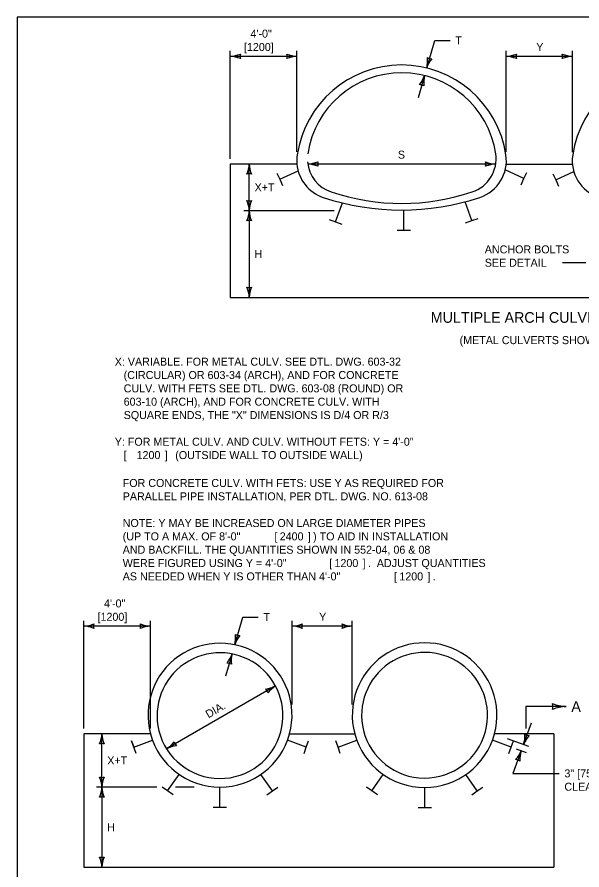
# Model space of a CAD drawing. Extents: x 49988.5 to 50021, y 49987.6 to 50011.4.
# Drawn here: x 50000.34 to 50004.57, y 50004.87 to 50011.26 of the extents above; entities that cross this region are included whole.
import ezdxf

# ---------------------------------------------------------------- set-up
doc = ezdxf.new("R2010")
doc.units = 0
for name, color, linetype in [('Level 1', 7, 'Continuous'), ('Level 2', 7, 'Continuous'), ('Level 3', 7, 'Continuous'), ('Level 6', 7, 'Continuous')]:
    doc.layers.add(name, color=color, linetype=linetype)

msp = doc.modelspace()

# ---------------------------------------------------------------- linework, layer by layer
at = {"layer": 'Level 1'}
for p, q in [((50002.4328, 50010.1613), (50001.9329, 50010.1613)), ((50001.9329, 50010.1613), (50001.9329, 50009.1613)), ((50002.3043, 50010.0468), (50002.4418, 50010.1108)), ((50004.1337, 50010.0516), (50003.994, 50010.1169)), ((50004.0014, 50010.1613), (50004.4972, 50010.1613)), ((50002.2831, 50010.0921), (50002.3043, 50010.0468)), ((50002.3043, 50010.0468), (50002.3255, 50010.0015)), ((50004.1128, 50010.0064), (50004.1337, 50010.0516)), ((50004.1337, 50010.0516), (50004.1549, 50010.097)), ((50004.3508, 50010.087), (50004.372, 50010.0417)), ((50004.372, 50010.0417), (50004.5079, 50010.105)), ((50004.372, 50010.0417), (50004.3932, 50009.9964)), ((50002.7226, 50009.7286), (50002.7738, 50009.8696)), ((50003.744, 50009.737), (50003.6928, 50009.8778)), ((50003.2338, 50009.6659), (50003.2338, 50009.8159)), ((50002.6756, 50009.7458), (50002.7226, 50009.7286)), ((50002.7226, 50009.7286), (50002.7695, 50009.7115)), ((50003.6971, 50009.7198), (50003.744, 50009.737)), ((50003.744, 50009.737), (50003.7911, 50009.754)), ((50003.1838, 50009.6659), (50003.2338, 50009.6659)), ((50003.2338, 50009.6659), (50003.2838, 50009.6659)), ((50001.9329, 50009.1613), (50006.5462, 50009.1613)), ((50001.3352, 50005.8907), (50000.8356, 50005.8907)), ((50000.8356, 50005.8907), (50000.8356, 50004.8907)), ((50002.378, 50005.8907), (50002.866, 50005.8907)), ((50004.3574, 50005.8907), (50003.9135, 50005.8907)), ((50004.3574, 50005.8907), (50004.3574, 50004.8907)), ((50001.2103, 50005.7899), (50001.193, 50005.8369)), ((50001.193, 50005.8369), (50001.2103, 50005.7899)), ((50001.2103, 50005.7899), (50001.3507, 50005.842)), ((50002.5029, 50005.7899), (50002.3624, 50005.842)), ((50002.5029, 50005.7899), (50002.5202, 50005.8369)), ((50002.7409, 50005.7899), (50002.7236, 50005.8369)), ((50002.7409, 50005.7899), (50002.8814, 50005.8421)), ((50004.0385, 50005.7899), (50003.898, 50005.842)), ((50004.0385, 50005.7899), (50004.0558, 50005.8369)), ((50001.2273, 50005.7431), (50001.2103, 50005.7899)), ((50002.4859, 50005.7431), (50002.5029, 50005.7899)), ((50002.7579, 50005.7431), (50002.7409, 50005.7899)), ((50004.0215, 50005.7431), (50004.0385, 50005.7899)), ((50001.4641, 50005.4622), (50001.5501, 50005.5858)), ((50002.2491, 50005.4622), (50002.1631, 50005.5859)), ((50002.9947, 50005.4622), (50003.0803, 50005.5853)), ((50003.7847, 50005.4622), (50003.6991, 50005.5853)), ((50001.4641, 50005.4622), (50001.4231, 50005.4907)), ((50001.5049, 50005.4336), (50001.4641, 50005.4622)), ((50001.8551, 50005.3403), (50001.8551, 50005.4904)), ((50002.2083, 50005.4336), (50002.2491, 50005.4622)), ((50002.2491, 50005.4622), (50002.2901, 50005.4907)), ((50002.9947, 50005.4622), (50002.9537, 50005.4907)), ((50003.0355, 50005.4336), (50002.9947, 50005.4622)), ((50003.3902, 50005.3383), (50003.3902, 50005.4883)), ((50003.7439, 50005.4336), (50003.7847, 50005.4622)), ((50003.7847, 50005.4622), (50003.8257, 50005.4907)), ((50001.8051, 50005.3403), (50001.8551, 50005.3403)), ((50001.8551, 50005.3403), (50001.9051, 50005.3403)), ((50003.3402, 50005.3383), (50003.3902, 50005.3383)), ((50003.3902, 50005.3383), (50003.4402, 50005.3383)), ((50000.8356, 50004.8907), (50004.3574, 50004.8907))]:
    msp.add_line(p, q, dxfattribs=at)
msp.add_lwpolyline([(50008.6146, 50011.2628), (50000.3356, 50011.2628), (50000.3356, 50000.0624), (50008.6146, 50000.0624)], close=True, dxfattribs=at)
for centre, radius, start, end in [((50003.2171, 50010.1128), 0.7909, 8.49352, 171.50648), ((50005.2815, 50010.1128), 0.7909, 8.49352, 171.50648), ((50003.2184, 50010.1334), 0.7118, 8.49352, 171.50648), ((50003.6637, 50010.1999), 0.2615, 288.43689, 8.49352), ((50002.7223, 50010.1867), 0.2906, 171.50648, 185.01191), ((50002.7731, 50010.1999), 0.2615, 185.01218, 251.56311), ((50003.7119, 50010.1867), 0.2906, 288.43689, 8.49352), ((50004.7867, 50010.1867), 0.2906, 171.50648, 251.56311), ((50002.7223, 50010.1867), 0.2906, 185.01218, 251.56311), ((50003.2184, 50011.5357), 1.6696, 251.5631, 288.43689), ((50003.2171, 50011.6709), 1.8551, 251.5631, 288.43689), ((50001.8566, 50006.0301), 0.5397, 345.04213, 194.96009), ((50003.3897, 50006.0305), 0.5421, 345.06339, 194.93762), ((50001.8566, 50006.0262), 0.4718, 345.24996, 193.78371), ((50003.3897, 50006.029), 0.4718, 345.24996, 193.78371), ((50001.8566, 50006.0301), 0.5397, 194.95787, 345.04328), ((50001.8566, 50006.0277), 0.4721, 193.96469, 345.06898), ((50003.3897, 50006.0304), 0.5421, 194.92937, 345.07164), ((50003.3897, 50006.0305), 0.4721, 193.96469, 345.06898)]:
    msp.add_arc(centre, radius, start, end, dxfattribs=at)
at = {"layer": 'Level 3'}
for p, q in [((50003.4054, 50010.8809), (50003.4655, 50011.0878)), ((50003.4655, 50011.0878), (50003.5804, 50011.0878)), ((50001.9329, 50010.2013), (50001.9329, 50011.0084)), ((50002.4329, 50010.2527), (50002.4329, 50011.0084)), ((50004.0014, 50010.2521), (50004.0014, 50011.0084)), ((50004.4971, 50010.2498), (50004.4973, 50011.0084)), ((50002.4329, 50010.9684), (50001.9329, 50010.9684)), ((50004.4973, 50010.9684), (50004.0014, 50010.9684)), ((50003.3889, 50010.8244), (50003.3405, 50010.6578)), ((50002.0755, 50009.8113), (50002.0755, 50010.1613)), ((50003.9224, 50010.1613), (50002.5144, 50010.1613)), ((50002.7126, 50009.8111), (50002.0355, 50009.8114)), ((50002.0755, 50009.8113), (50002.0755, 50009.1613)), ((50004.5977, 50009.4215), (50004.4234, 50009.4215)), ((50000.8356, 50005.9307), (50000.8356, 50006.7378)), ((50001.3356, 50005.9307), (50001.3356, 50006.7378)), ((50001.9669, 50006.5584), (50002.027, 50006.7652)), ((50002.027, 50006.7652), (50002.1419, 50006.7652)), ((50002.3963, 50006.1108), (50002.3963, 50006.7378)), ((50002.8477, 50006.1106), (50002.8479, 50006.7378)), ((50001.3356, 50006.6978), (50000.8356, 50006.6978)), ((50002.8479, 50006.6978), (50002.3963, 50006.6978)), ((50001.9467, 50006.4892), (50001.8983, 50006.3226)), ((50002.2721, 50006.2494), (50001.4558, 50005.7781)), ((50004.1316, 50005.811), (50004.1911, 50005.9739)), ((50000.9714, 50005.4907), (50000.9714, 50005.8907)), ((50004.0078, 50005.8564), (50004.1692, 50005.7973)), ((50004.114, 50005.7631), (50004.0518, 50005.594)), ((50004.0763, 50005.7769), (50004.1516, 50005.7495)), ((50004.0745, 50005.6551), (50004.0518, 50005.594)), ((50004.0518, 50005.594), (50004.3974, 50005.594)), ((50001.3831, 50005.4907), (50000.9314, 50005.4907)), ((50000.9714, 50005.4907), (50000.9714, 50004.8907)), ((50001.6632, 50005.4907), (50001.5239, 50005.4907))]:
    msp.add_line(p, q, dxfattribs=at)
for centre, radius, start, end in [((50001.9214, 50011.2011), 0.233, 272.82731, 292.07716), ((50001.9237, 50010.7463), 0.2223, 67.45601, 87.63952), ((50002.0611, 50010.9684), 0.0548, 162.13882, 197.86118), ((50002.4421, 50011.1905), 0.2223, 247.45601, 267.63952), ((50002.3047, 50010.9684), 0.0548, 342.13882, 17.86118), ((50002.4444, 50010.7357), 0.233, 92.82731, 112.07716), ((50003.1787, 50010.9349), 0.233, 346.60967, 5.85952), ((50003.6161, 50010.8101), 0.2223, 141.23837, 161.42188), ((50003.4412, 50011.0041), 0.0548, 235.92118, 271.64354), ((50003.9899, 50011.2011), 0.233, 272.82731, 292.07716), ((50003.9922, 50010.7463), 0.2223, 67.45601, 87.63952), ((50004.1296, 50010.9684), 0.0548, 162.13882, 197.86118), ((50004.5065, 50011.1905), 0.2223, 247.45601, 267.63952), ((50004.3691, 50010.9684), 0.0548, 342.13882, 17.86118), ((50004.5088, 50010.7357), 0.233, 92.82731, 112.07716), ((50003.1782, 50010.8953), 0.2223, 321.23837, 341.42188), ((50003.6156, 50010.7705), 0.233, 166.60967, 185.85952), ((50003.3531, 50010.7013), 0.0548, 55.92118, 91.64354), ((50002.5029, 50010.394), 0.233, 272.82731, 292.07716), ((50002.6426, 50010.1613), 0.0548, 162.13882, 197.86118), ((50003.9316, 50010.3834), 0.2223, 247.45601, 267.63952), ((50003.7942, 50010.1613), 0.0548, 342.13882, 17.86118), ((50001.8534, 50010.1705), 0.2223, 337.45601, 357.63952), ((50002.3082, 50010.1728), 0.233, 182.82731, 202.07716), ((50002.5053, 50009.9392), 0.2223, 67.45601, 87.63952), ((50003.9339, 50009.9286), 0.233, 92.82731, 112.07716), ((50002.0755, 50010.0331), 0.0548, 72.13882, 107.86118), ((50002.0755, 50009.9395), 0.0548, 252.13882, 287.86118), ((50001.8428, 50009.7998), 0.233, 2.82731, 22.07716), ((50002.2976, 50009.8021), 0.2223, 157.45601, 177.63952), ((50001.8534, 50009.8205), 0.2223, 337.45601, 357.63952), ((50002.3082, 50009.8228), 0.233, 182.82731, 202.07716), ((50002.0755, 50009.6831), 0.0548, 72.13882, 107.86118), ((50002.0755, 50009.2895), 0.0548, 252.13882, 287.86118), ((50001.8428, 50009.1498), 0.233, 2.82731, 22.07716), ((50002.2976, 50009.1521), 0.2223, 157.45601, 177.63952), ((50000.8241, 50006.9305), 0.233, 272.82731, 292.07716), ((50000.8264, 50006.4757), 0.2223, 67.45601, 87.63952), ((50000.9638, 50006.6978), 0.0548, 162.13882, 197.86118), ((50001.3448, 50006.92), 0.2223, 247.45601, 267.63952), ((50001.2074, 50006.6978), 0.0548, 342.13882, 17.86118), ((50001.3471, 50006.4651), 0.233, 92.82731, 112.07716), ((50002.3848, 50006.9305), 0.233, 272.82731, 292.07716), ((50002.3871, 50006.4757), 0.2223, 67.45601, 87.63952), ((50002.5245, 50006.6978), 0.0548, 162.13882, 197.86118), ((50002.857, 50006.92), 0.2223, 247.45601, 267.63952), ((50002.7197, 50006.6978), 0.0548, 342.13882, 17.86118), ((50002.8594, 50006.4651), 0.233, 92.82731, 112.07716), ((50001.7402, 50006.6123), 0.233, 346.60967, 5.85952), ((50002.1776, 50006.4875), 0.2223, 141.23837, 161.42188), ((50002.0027, 50006.6815), 0.0548, 235.92118, 271.64354), ((50001.736, 50006.56), 0.2223, 321.23837, 341.42188), ((50002.1734, 50006.4353), 0.233, 166.60967, 185.85952), ((50001.9109, 50006.3661), 0.0548, 55.92118, 91.64354), ((50002.169, 50006.4464), 0.2223, 277.45977, 297.64328), ((50002.1611, 50006.1853), 0.0548, 12.14257, 47.86494), ((50002.3985, 50006.0536), 0.233, 122.83107, 142.08092), ((50000.7493, 50005.8999), 0.2223, 337.45601, 357.63952), ((50001.2041, 50005.9022), 0.233, 182.82731, 202.07716), ((50003.9091, 50005.8801), 0.233, 342.75579, 2.00564), ((50004.1756, 50005.9314), 0.0548, 232.06729, 267.78966), ((50001.3295, 50005.9738), 0.233, 302.83107, 322.08092), ((50001.5669, 50005.8422), 0.0548, 192.14257, 227.86494), ((50004.3371, 50005.7262), 0.2223, 137.38449, 157.56799), ((50000.9714, 50005.7625), 0.0548, 72.13882, 107.86118), ((50001.559, 50005.5811), 0.2223, 97.45977, 117.64328), ((50003.9085, 50005.848), 0.2223, 317.37296, 337.55647), ((50004.3365, 50005.694), 0.233, 162.74426, 181.99411), ((50004.07, 50005.6427), 0.0548, 52.05577, 87.77813), ((50000.9714, 50005.619), 0.0548, 252.13882, 287.86118), ((50000.7387, 50005.4792), 0.233, 2.82731, 22.07716), ((50001.1935, 50005.4816), 0.2223, 157.45601, 177.63952), ((50000.7493, 50005.4999), 0.2223, 337.45601, 357.63952), ((50001.2041, 50005.5022), 0.233, 182.82731, 202.07716), ((50000.9714, 50005.3625), 0.0548, 72.13882, 107.86118), ((50000.9714, 50005.019), 0.0548, 252.13882, 287.86118), ((50000.7387, 50004.8792), 0.233, 2.82731, 22.07716), ((50001.1935, 50004.8816), 0.2223, 157.45601, 177.63952)]:
    msp.add_arc(centre, radius, start, end, dxfattribs=at)
at = {"layer": 'Level 6'}
for p, q in [((50004.4493, 50006.0952), (50004.1493, 50006.0952)), ((50004.1493, 50006.0952), (50004.1493, 50005.9307))]:
    msp.add_line(p, q, dxfattribs=at)
for centre, radius, start, end in [((50004.4615, 50006.3914), 0.2964, 247.45601, 267.63952), ((50004.2783, 50006.0952), 0.073, 342.13882, 17.86118), ((50004.4646, 50005.785), 0.3107, 92.82731, 112.07716)]:
    msp.add_arc(centre, radius, start, end, dxfattribs=at)

# ---------------------------------------------------------------- texts
at = {"layer": 'Level 2'}
for s, height, p in [('4\'-0"', 0.06, (50002.0846, 50011.1084)), ('[1200]', 0.06, (50002.0359, 50011.0084)), ('T', 0.06, (50003.6204, 50011.0578)), ('Y', 0.06, (50004.2265, 50011.0084)), ('S', 0.06, (50003.1894, 50010.2013)), ('X+T', 0.06, (50002.1155, 50009.9563)), ('ANCHOR BOLTS', 0.06, (50003.8405, 50009.4915)), ('H', 0.06, (50002.1155, 50009.4563)), ('SEE DETAIL', 0.06, (50003.8405, 50009.3915)), ('MULTIPLE ARCH CULVERTS', 0.08, (50003.4357, 50008.9713)), ('(METAL CULVERTS SHOWN)', 0.06, (50003.6518, 50008.8113)), ('X: VARIABLE. FOR METAL CULV. SEE DTL. DWG. 603-32 ', 0.06, (50001.0677, 50008.6498)), ('   (CIRCULAR) OR 603-34 (ARCH), AND FOR CONCRETE ', 0.06, (50001.0677, 50008.5498)), ('   CULV. WITH FETS SEE DTL. DWG. 603-08 (ROUND) OR ', 0.06, (50001.0677, 50008.4498)), ('   603-10 (ARCH), AND FOR CONCRETE CULV. WITH ', 0.06, (50001.0677, 50008.3498)), ('   SQUARE ENDS, THE "X" DIMENSIONS IS D/4 OR R/3', 0.06, (50001.0677, 50008.2498)), ('Y: FOR METAL CULV. AND CULV. WITHOUT FETS: Y = 4\'-0"', 0.06, (50001.0677, 50008.0498)), ('   [', 0.06, (50001.0677, 50007.9498)), ('1200', 0.06, (50001.2312, 50007.9498)), ('] ', 0.06, (50001.4417, 50007.9498)), ('(OUTSIDE WALL TO OUTSIDE WALL)', 0.06, (50001.521, 50007.9498)), ('   FOR CONCRETE CULV. WITH FETS: USE Y AS REQUIRED FOR', 0.06, (50001.0605, 50007.7405)), ('   PARALLEL PIPE INSTALLATION, PER DTL. DWG. NO. 613-08', 0.06, (50001.0605, 50007.6405)), ('   NOTE: Y MAY BE INCREASED ON LARGE DIAMETER PIPES', 0.06, (50001.0605, 50007.4405)), ('   (UP TO A MAX. OF 8\'-0" ', 0.06, (50001.0605, 50007.3405)), ('[', 0.06, (50002.2642, 50007.3405)), ('2400', 0.06, (50002.3039, 50007.3405)), (']', 0.06, (50002.5144, 50007.3405)), (') TO AID IN INSTALLATION', 0.06, (50002.5541, 50007.3405)), ('   AND BACKFILL. THE QUANTITIES SHOWN IN 552-04, 06 & 08', 0.06, (50001.0605, 50007.2405)), ('   WERE FIGURED USING Y = 4\'-0" ', 0.06, (50001.0605, 50007.1405)), ('[', 0.06, (50002.6747, 50007.1405)), ('1200', 0.06, (50002.7144, 50007.1405)), (']', 0.06, (50002.9249, 50007.1405)), ('.  ADJUST QUANTITIES', 0.06, (50002.9646, 50007.1405)), ('   AS NEEDED WHEN Y IS OTHER THAN 4\'-0" ', 0.06, (50001.0605, 50007.0405)), ('[', 0.06, (50003.1607, 50007.0405)), ('1200', 0.06, (50003.2004, 50007.0405)), (']', 0.06, (50003.4108, 50007.0405)), ('.  ', 0.06, (50003.4505, 50007.0405)), ('4\'-0"', 0.06, (50000.9873, 50006.8378)), ('[1200]', 0.06, (50000.9386, 50006.7378)), ('T', 0.06, (50002.1819, 50006.7352)), ('Y', 0.06, (50002.5992, 50006.7378)), ('A', 0.08, (50004.4893, 50006.0552)), ('X+T', 0.06, (50001.0114, 50005.6607)), ('3" [75] MIN.', 0.06, (50004.4374, 50005.564)), ('CLEARANCE', 0.06, (50004.4374, 50005.464)), ('H', 0.06, (50001.0114, 50005.1607))]:
    msp.add_text(s, height=height, dxfattribs=at).set_placement(p)
msp.add_text('DIA.', height=0.06, rotation=30.00376, dxfattribs=at).set_placement((50001.7698, 50006.0055))

doc.saveas('drawing.dxf')
